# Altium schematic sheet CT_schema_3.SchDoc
size 283 x 174 mm
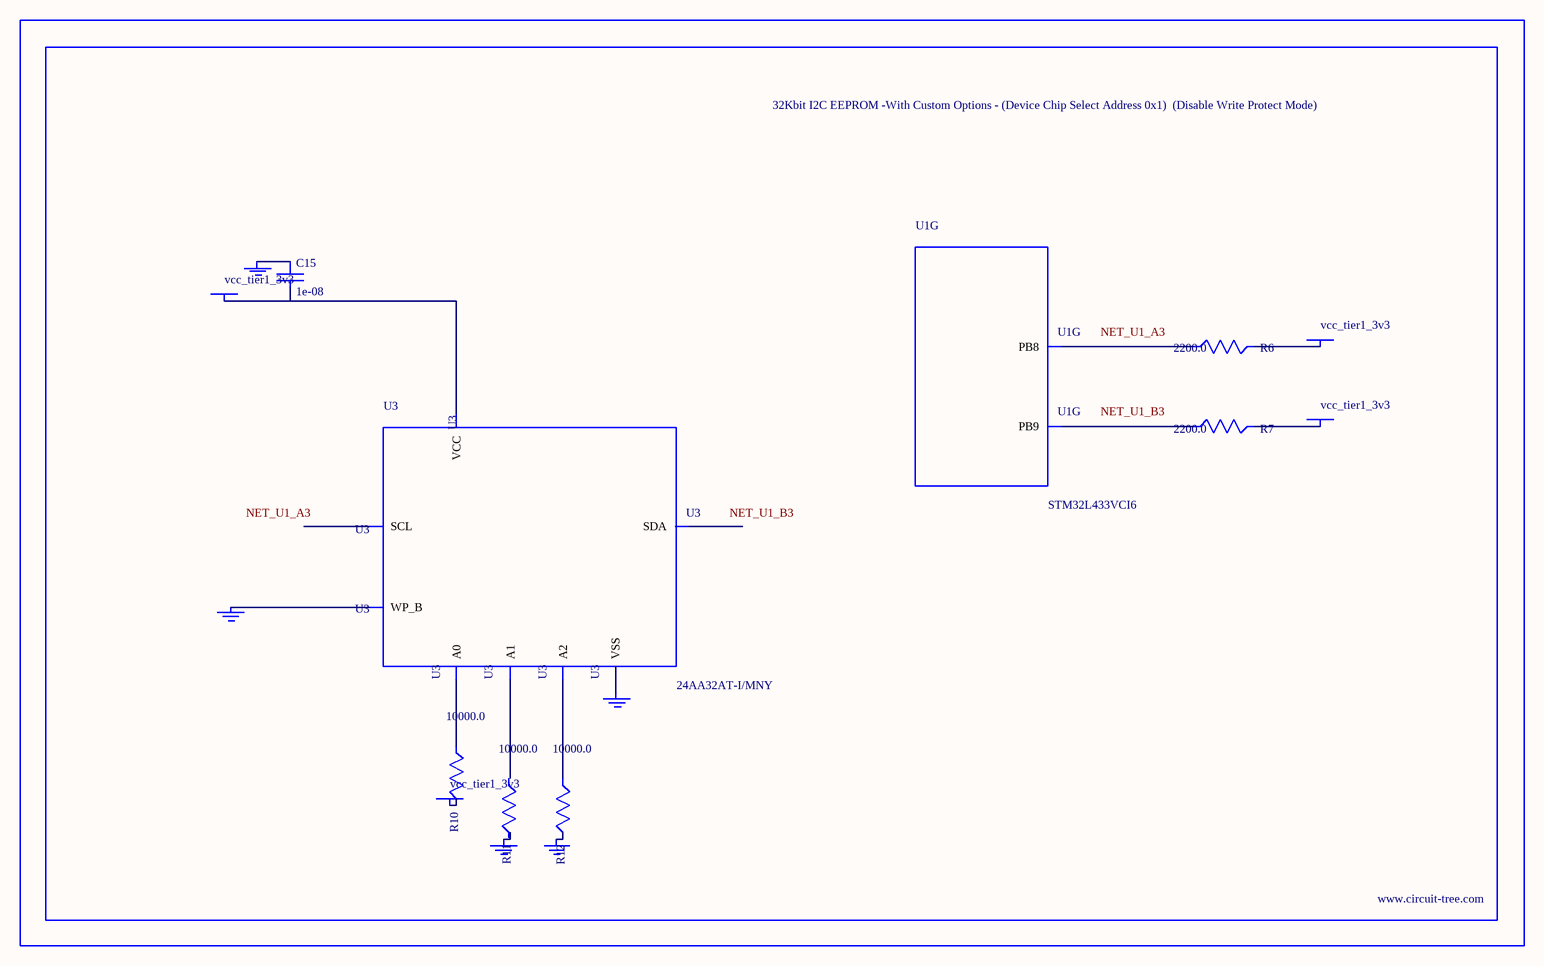
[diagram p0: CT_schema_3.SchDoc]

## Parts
BORDER2  (no value)
C15  1e-08  [C0402]
GND_INSTANCE_2_0  (no value)
GND_INSTANCE_2_1  (no value)
GND_INSTANCE_2_2  (no value)
GND_INSTANCE_2_3  (no value)
GND_INSTANCE_2_4  (no value)
POWER_INSTANCE_2_0  vcc_tier1_3v3
POWER_INSTANCE_2_1  vcc_tier1_3v3
POWER_INSTANCE_2_2  vcc_tier1_3v3
POWER_INSTANCE_2_3  vcc_tier1_3v3
R6  2200.0  [R0603]
R7  2200.0  [R0603]
R10  10000.0  [R0603]
R11  10000.0  [R0603]
R12  10000.0  [R0603]
U1  STM32L433VCI6  [UFBGA100]  (part G of 11)
U3  24AA32AT-I/MNY  [TDFN-8/6MM]

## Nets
NetC15_1: C15.1 GND_INSTANCE_2_3.0(GND)
NetC15_2: C15.2 POWER_INSTANCE_2_1.0(PWR) U3.8(VCC)
NetGND_INSTANCE_2_1_0: GND_INSTANCE_2_1.0(GND) R12.2
NetGND_INSTANCE_2_2_0: GND_INSTANCE_2_2.0(GND) U3.7(WP_B)
NetGND_INSTANCE_2_4_0: GND_INSTANCE_2_4.0(GND) U3.4(VSS)
NetPOWER_INSTANCE_2_0_0: POWER_INSTANCE_2_0.0(PWR) R10.2
NetPOWER_INSTANCE_2_2_0: POWER_INSTANCE_2_2.0(PWR) R6.2
NetPOWER_INSTANCE_2_3_0: POWER_INSTANCE_2_3.0(PWR) R7.2
NetR6_1: R6.1 U1.A3(PB8)
NetR7_1: R7.1 U1.B3(PB9)
NetR10_1: R10.1 U3.1(A0)
NetR12_1: R12.1 U3.3(A2)

Not connected (* = marked no-connect by the designer): GND_INSTANCE_2_0 0(GND); R11 1 2; U3 2(A1) 5(SDA) 6(SCL)

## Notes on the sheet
- Labels drawn without touching a wire or pin: NET_U1_A3, NET_U1_B3

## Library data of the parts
BORDER2 = BORDER_PAGE2
C15 = C0402C103K3RAC
GND_INSTANCE_2_0-GND_INSTANCE_2_4 = GND
POWER_INSTANCE_2_0-POWER_INSTANCE_2_3 = PWR
R6 R7 = RC0603JR-072K2L
R10-R12 = RC0603JR-0710KL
